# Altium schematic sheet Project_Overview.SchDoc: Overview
size A4; Date: Not used; ApprovedBy: Not used; CheckedBy: Not used; Author: Not used; CompanyName: STMicroelectronics; DrawnBy: Not used; Engineer: Not used; Organization: Not used; Address1: Not used; Address2: Not used; Address3: Not used; Address4: Not used; DocumentNumber: Not used; Revision: Not used; SheetNumber: 1; SheetTotal: 12
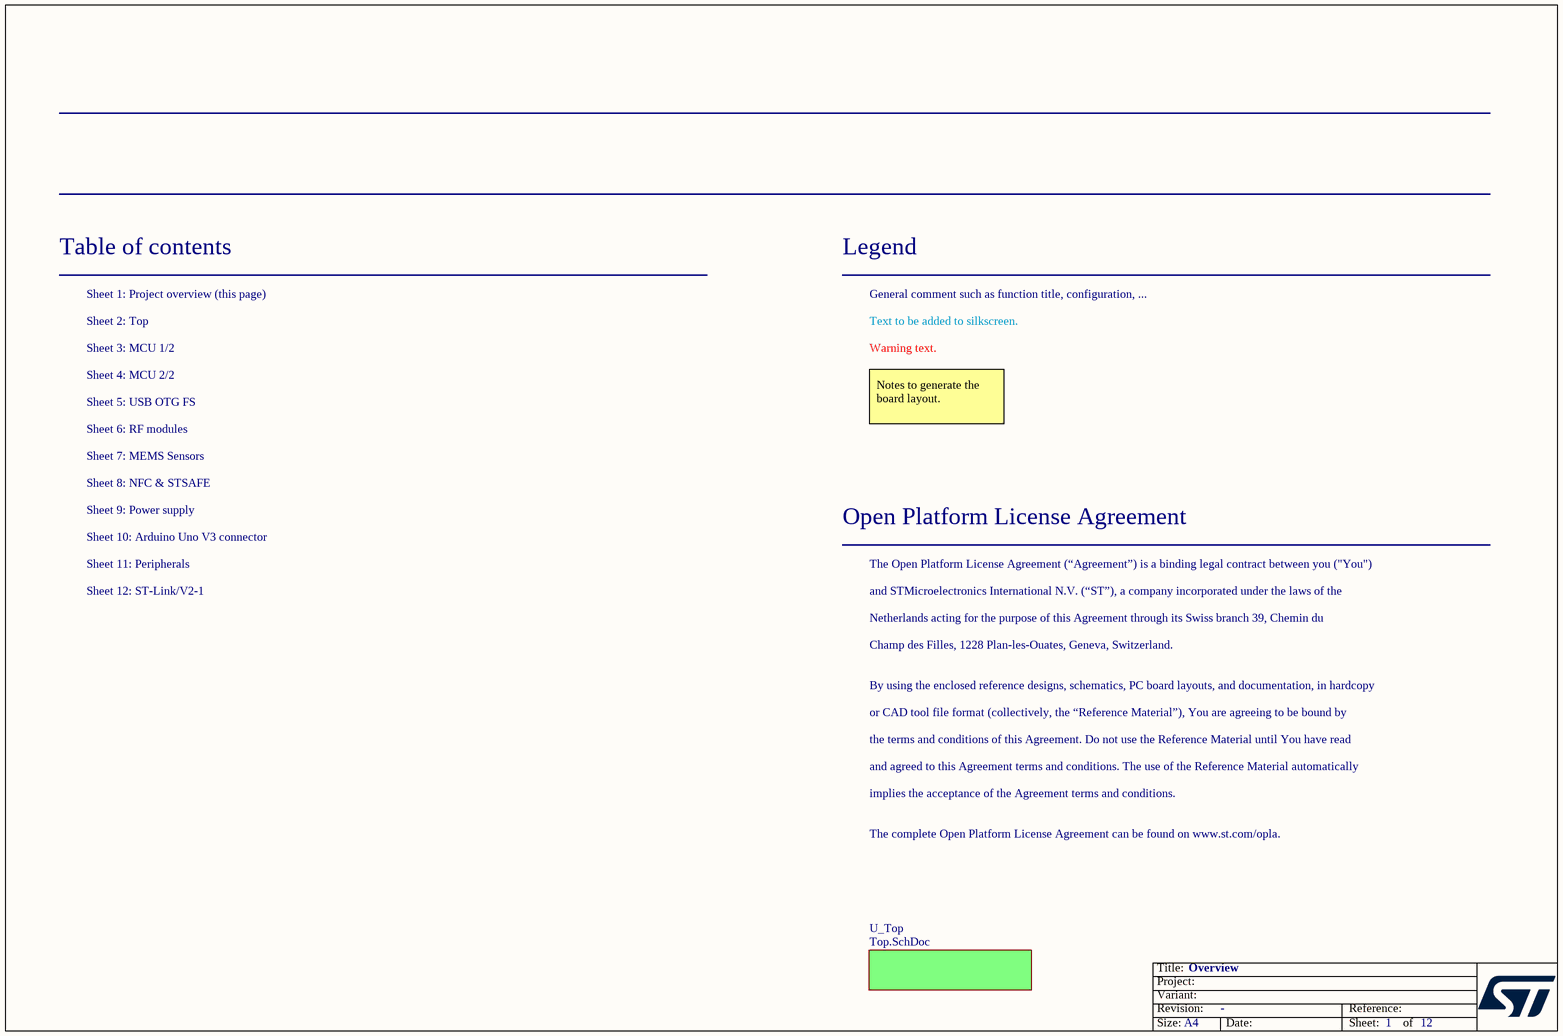
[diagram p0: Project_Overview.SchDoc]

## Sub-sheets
U_Top = Top.SchDoc: no entries

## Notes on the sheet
- Table of contents
- Sheet 1: Project overview (this page)
- Legend
- General comment such as function title, configuration, ...
- Sheet 2: Top
- Sheet 3: MCU 1/2
- Sheet 4: MCU 2/2
- Text to be added to silkscreen.
- Warning text.
- Sheet 6: RF modules
- Sheet 5: USB OTG FS
- Notes to generate the board layout.
- Sheet 7: MEMS Sensors
- Sheet 8: NFC & STSAFE
- Sheet 9: Power supply
- Sheet 10: Arduino Uno V3 connector
- Sheet 11: Peripherals
- Open Platform License Agreement
- The Open Platform License Agreement (“Agreement”) is a binding legal contract between you ("You")
- Sheet 12: ST-Link/V2-1
- and STMicroelectronics International N.V. (“ST”), a company incorporated under the laws of the
- Netherlands acting for the purpose of this Agreement through its Swiss branch 39, Chemin du
- Champ des Filles, 1228 Plan-les-Ouates, Geneva, Switzerland.
- By using the enclosed reference designs, schematics, PC board layouts, and documentation, in hardcopy
- or CAD tool file format (collectively, the “Reference Material”), You are agreeing to be bound by
- the terms and conditions of this Agreement. Do not use the Reference Material until You have read
- and agreed to this Agreement terms and conditions. The use of the Reference Material automatically
- implies the acceptance of the Agreement terms and conditions.
- The complete Open Platform License Agreement can be found on www.st.com/opla.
